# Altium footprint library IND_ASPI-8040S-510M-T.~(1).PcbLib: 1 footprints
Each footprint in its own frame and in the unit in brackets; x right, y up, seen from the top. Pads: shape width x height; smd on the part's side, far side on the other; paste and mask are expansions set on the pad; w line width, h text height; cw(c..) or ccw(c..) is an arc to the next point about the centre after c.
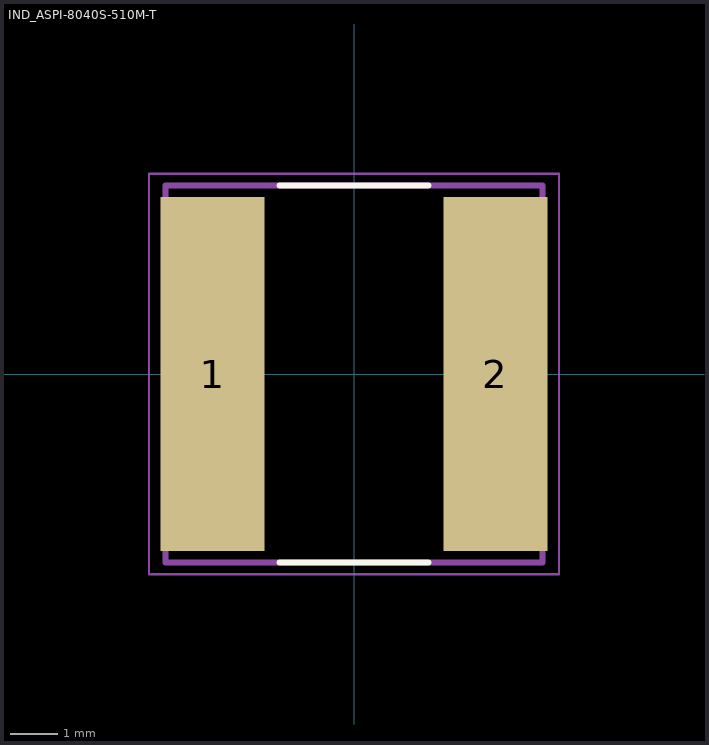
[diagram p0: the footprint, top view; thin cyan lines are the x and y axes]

## IND_ASPI-8040S-510M-T [mm]
height 4.2
pads (2):
  rect 2.2x7.5 smd: 1(-3,0) 2(3,0)
Top Overlay:
  lines w0.127: -1.58,-4 1.58,-4 ; -1.58,4 1.58,4
Mechanical 13:
  lines w0.127: -4,-4 -4,4 4,4 4,-4 -4,-4
Mechanical 15:
  lines w0.05: -4.35,-4.25 -4.35,4.25 4.35,4.25 4.35,-4.25 -4.35,-4.25
3D body "step_temp.STEP": height 4, standoff 0, extent -4,-4 4,4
